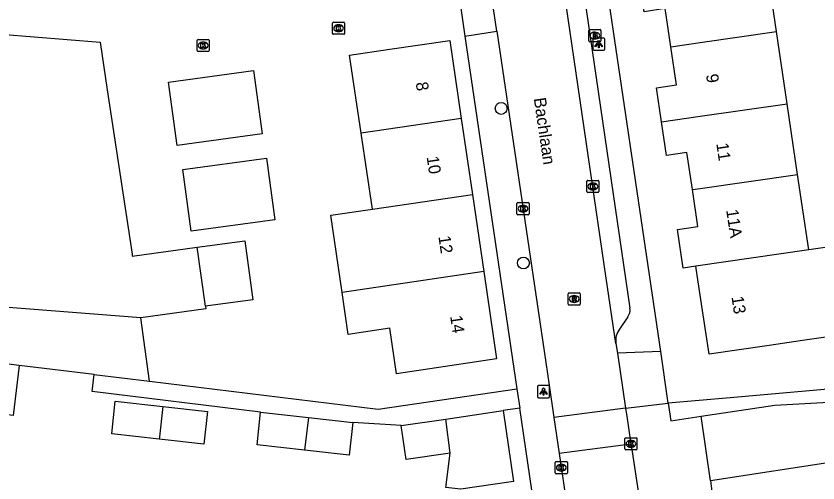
# Model space of a CAD drawing. Extents: x 159053 to 160041, y 380450 to 381422.
# Drawn here: x 159443.6 to 159509.7, y 381207.2 to 381245.7 of the extents above; entities that cross this region are included whole.
import ezdxf

# ---------------------------------------------------------------- set-up
doc = ezdxf.new("R2010")
doc.units = 0
for name, color, linetype in [('IMGEO_Boom', 7, 'Continuous'), ('IMGEO_Brandkraan', 7, 'Continuous'), ('IMGEO_Kolk', 7, 'Continuous'), ('IMGEO_Lichtpunt', 7, 'Continuous'), ('IMGEO_Openbare_ruimte_label', 7, 'Continuous'), ('IMGEO_Pand', 7, 'Continuous'), ('IMGEO_Pand_nummerreeks', 7, 'Continuous'), ('IMGEO_Rijbaan_lokaal_open', 7, 'Continuous'), ('IMGEO_Rioolput', 7, 'Continuous'), ('IMGEO_Voetpad_open', 7, 'Continuous')]:
    doc.layers.add(name, color=color, linetype=linetype)

msp = doc.modelspace()

# ---------------------------------------------------------------- linework, layer by layer
at = {"layer": 'IMGEO_Boom'}
for centre in [(159483.6, 381238.048), (159485.436, 381225.309)]:
    msp.add_circle(centre, 0.489, dxfattribs=at)
at = {"layer": 'IMGEO_Brandkraan'}
for p, q in [((159490.822, 381243.628), (159490.822, 381244.48)), ((159490.897, 381244.554), (159491.749, 381244.554)), ((159491.823, 381244.48), (159491.823, 381243.628)), ((159491.31, 381244.334), (159491.335, 381244.334)), ((159491.749, 381243.554), (159490.897, 381243.554)), ((159491.333, 381243.774), (159491.308, 381243.774))]:
    msp.add_line(p, q, dxfattribs=at)
for points in [[(159490.822, 381243.628), (159490.822, 381244.48)], [(159490.897, 381244.554), (159491.749, 381244.554)], [(159491.823, 381244.48), (159491.823, 381243.628)], [(159491.17, 381244.254), (159491.17, 381243.854), (159491.383, 381243.854)], [(159491.401, 381244.254), (159491.17, 381244.254)], [(159491.349, 381244.173), (159491.295, 381244.173), (159491.295, 381244.097)], [(159491.295, 381244.097), (159491.348, 381244.097)], [(159491.357, 381244.021), (159491.295, 381244.021), (159491.295, 381243.94)], [(159491.295, 381243.94), (159491.357, 381243.94)], [(159491.749, 381243.554), (159490.897, 381243.554)]]:
    msp.add_lwpolyline(points, dxfattribs=at)
for centre, radius, start, end in [((159490.899, 381244.478), 0.0765, 91.55205, 178.44795), ((159490.899, 381244.478), 0.0765, 91.55205, 178.44795), ((159491.747, 381244.478), 0.0765, 1.55205, 88.44795), ((159491.747, 381244.478), 0.0765, 1.55205, 88.44795), ((159491.35, 381244.135), 0.0379, 267.82845, 90.93552), ((159491.358, 381243.98), 0.0404, 269.87594, 90.50774), ((159491.389, 381244.105), 0.251, 268.66757, 293.53466), ((159491.405, 381244.109), 0.145, 59.4692, 91.53667), ((159491.43, 381244.156), 0.0922, 285.51372, 58.15012), ((159491.435, 381243.964), 0.105, 301.31148, 78.98903), ((159490.899, 381243.63), 0.0765, 181.55205, 268.44795), ((159490.899, 381243.63), 0.0765, 181.55205, 268.44795), ((159491.747, 381243.63), 0.0765, 271.55205, 358.44795), ((159491.747, 381243.63), 0.0765, 271.55205, 358.44795)]:
    msp.add_arc(centre, radius, start, end, dxfattribs=at)
for centre, major_axis, ratio, start_param, end_param in [((159491.309, 381244.054), (-0.387, 0.002), 0.722429, 4.712389, 7.853982), ((159491.334, 381244.054), (-0.39, 0.002), 0.717154, 1.570796, 4.712389)]:
    msp.add_ellipse(centre, major_axis=major_axis, ratio=ratio, start_param=start_param, end_param=end_param, dxfattribs=at)
at = {"layer": 'IMGEO_Kolk'}
for p, q in [((159469.776, 381245.161), (159470.628, 381245.161)), ((159469.701, 381244.235), (159469.701, 381245.087)), ((159470.189, 381244.941), (159470.214, 381244.941)), ((159470.702, 381245.087), (159470.702, 381244.235)), ((159470.628, 381244.161), (159469.776, 381244.161)), ((159470.212, 381244.381), (159470.187, 381244.381)), ((159458.545, 381242.813), (159458.545, 381243.665)), ((159458.62, 381243.739), (159459.472, 381243.739)), ((159459.033, 381243.519), (159459.058, 381243.519)), ((159459.546, 381243.665), (159459.546, 381242.813)), ((159459.472, 381242.739), (159458.62, 381242.739)), ((159459.056, 381242.959), (159459.031, 381242.959)), ((159490.655, 381231.192), (159490.655, 381232.044)), ((159490.73, 381232.118), (159491.582, 381232.118)), ((159491.656, 381232.044), (159491.656, 381231.192)), ((159491.166, 381231.338), (159491.141, 381231.338)), ((159491.143, 381231.898), (159491.168, 381231.898)), ((159491.582, 381231.118), (159490.73, 381231.118)), ((159484.903, 381229.361), (159484.903, 381230.213)), ((159484.978, 381230.287), (159485.83, 381230.287)), ((159485.391, 381230.067), (159485.416, 381230.067)), ((159485.904, 381230.213), (159485.904, 381229.361)), ((159485.83, 381229.287), (159484.978, 381229.287)), ((159485.414, 381229.507), (159485.389, 381229.507)), ((159493.793, 381209.974), (159493.793, 381210.826)), ((159493.868, 381210.9), (159494.72, 381210.9)), ((159494.794, 381210.826), (159494.794, 381209.974)), ((159494.304, 381210.12), (159494.279, 381210.12)), ((159494.281, 381210.68), (159494.306, 381210.68)), ((159494.72, 381209.9), (159493.868, 381209.9)), ((159488.059, 381208.008), (159488.059, 381208.86)), ((159488.134, 381208.934), (159488.986, 381208.934)), ((159489.06, 381208.86), (159489.06, 381208.008)), ((159488.57, 381208.154), (159488.545, 381208.154)), ((159488.547, 381208.714), (159488.572, 381208.714)), ((159488.986, 381207.934), (159488.134, 381207.934))]:
    msp.add_line(p, q, dxfattribs=at)
for points in [[(159469.776, 381245.161), (159470.628, 381245.161)], [(159469.701, 381244.235), (159469.701, 381245.087)], [(159470.022, 381244.861), (159470.145, 381244.861), (159470.145, 381244.71), (159470.275, 381244.861), (159470.439, 381244.861), (159470.293, 381244.71), (159470.446, 381244.461), (159470.294, 381244.461), (159470.209, 381244.625), (159470.145, 381244.558), (159470.145, 381244.461), (159470.022, 381244.461), (159470.022, 381244.861)], [(159470.702, 381245.087), (159470.702, 381244.235)], [(159470.628, 381244.161), (159469.776, 381244.161)], [(159458.545, 381242.813), (159458.545, 381243.665)], [(159458.62, 381243.739), (159459.472, 381243.739)], [(159458.866, 381243.439), (159458.989, 381243.439), (159458.989, 381243.288), (159459.119, 381243.439), (159459.283, 381243.439), (159459.137, 381243.288), (159459.29, 381243.039), (159459.138, 381243.039), (159459.053, 381243.203), (159458.989, 381243.136), (159458.989, 381243.039), (159458.866, 381243.039), (159458.866, 381243.439)], [(159459.546, 381243.665), (159459.546, 381242.813)], [(159459.472, 381242.739), (159458.62, 381242.739)], [(159490.655, 381231.192), (159490.655, 381232.044)], [(159490.73, 381232.118), (159491.582, 381232.118)], [(159491.656, 381232.044), (159491.656, 381231.192)], [(159490.976, 381231.818), (159491.099, 381231.818), (159491.099, 381231.667), (159491.229, 381231.818), (159491.393, 381231.818), (159491.247, 381231.667), (159491.4, 381231.418), (159491.248, 381231.418), (159491.163, 381231.582), (159491.099, 381231.515), (159491.099, 381231.418), (159490.976, 381231.418), (159490.976, 381231.818)], [(159491.582, 381231.118), (159490.73, 381231.118)], [(159484.903, 381229.361), (159484.903, 381230.213)], [(159484.978, 381230.287), (159485.83, 381230.287)], [(159485.224, 381229.987), (159485.347, 381229.987), (159485.347, 381229.836), (159485.477, 381229.987), (159485.641, 381229.987), (159485.495, 381229.836), (159485.648, 381229.587), (159485.496, 381229.587), (159485.411, 381229.751), (159485.347, 381229.684), (159485.347, 381229.587), (159485.224, 381229.587), (159485.224, 381229.987)], [(159485.904, 381230.213), (159485.904, 381229.361)], [(159485.83, 381229.287), (159484.978, 381229.287)], [(159493.793, 381209.974), (159493.793, 381210.826)], [(159493.868, 381210.9), (159494.72, 381210.9)], [(159494.794, 381210.826), (159494.794, 381209.974)], [(159494.114, 381210.6), (159494.237, 381210.6), (159494.237, 381210.449), (159494.367, 381210.6), (159494.531, 381210.6), (159494.385, 381210.449), (159494.538, 381210.2), (159494.386, 381210.2), (159494.301, 381210.364), (159494.237, 381210.297), (159494.237, 381210.2), (159494.114, 381210.2), (159494.114, 381210.6)], [(159494.72, 381209.9), (159493.868, 381209.9)], [(159488.059, 381208.008), (159488.059, 381208.86)], [(159488.134, 381208.934), (159488.986, 381208.934)], [(159489.06, 381208.86), (159489.06, 381208.008)], [(159488.38, 381208.634), (159488.503, 381208.634), (159488.503, 381208.483), (159488.633, 381208.634), (159488.797, 381208.634), (159488.651, 381208.483), (159488.804, 381208.234), (159488.652, 381208.234), (159488.567, 381208.398), (159488.503, 381208.331), (159488.503, 381208.234), (159488.38, 381208.234), (159488.38, 381208.634)], [(159488.986, 381207.934), (159488.134, 381207.934)]]:
    msp.add_lwpolyline(points, dxfattribs=at)
for centre, start, end in [((159469.778, 381245.085), 91.55205, 178.44795), ((159469.778, 381245.085), 91.55205, 178.44795), ((159470.626, 381245.085), 1.55205, 88.44795), ((159470.626, 381245.085), 1.55205, 88.44795), ((159469.778, 381244.237), 181.55205, 268.44795), ((159469.778, 381244.237), 181.55205, 268.44795), ((159470.626, 381244.237), 271.55205, 358.44795), ((159470.626, 381244.237), 271.55205, 358.44795), ((159458.622, 381243.663), 91.55205, 178.44795), ((159458.622, 381243.663), 91.55205, 178.44795), ((159459.47, 381243.663), 1.55205, 88.44795), ((159459.47, 381243.663), 1.55205, 88.44795), ((159458.622, 381242.815), 181.55205, 268.44795), ((159458.622, 381242.815), 181.55205, 268.44795), ((159459.47, 381242.815), 271.55205, 358.44795), ((159459.47, 381242.815), 271.55205, 358.44795), ((159490.732, 381232.042), 91.55205, 178.44795), ((159490.732, 381232.042), 91.55205, 178.44795), ((159491.58, 381232.042), 1.55205, 88.44795), ((159491.58, 381232.042), 1.55205, 88.44795), ((159490.732, 381231.194), 181.55205, 268.44795), ((159490.732, 381231.194), 181.55205, 268.44795), ((159491.58, 381231.194), 271.55205, 358.44795), ((159491.58, 381231.194), 271.55205, 358.44795), ((159484.98, 381230.211), 91.55205, 178.44795), ((159484.98, 381230.211), 91.55205, 178.44795), ((159485.828, 381230.211), 1.55205, 88.44795), ((159485.828, 381230.211), 1.55205, 88.44795), ((159484.98, 381229.363), 181.55205, 268.44795), ((159484.98, 381229.363), 181.55205, 268.44795), ((159485.828, 381229.363), 271.55205, 358.44795), ((159485.828, 381229.363), 271.55205, 358.44795), ((159493.87, 381210.824), 91.55205, 178.44795), ((159493.87, 381210.824), 91.55205, 178.44795), ((159494.718, 381210.824), 1.55205, 88.44795), ((159494.718, 381210.824), 1.55205, 88.44795), ((159493.87, 381209.976), 181.55205, 268.44795), ((159493.87, 381209.976), 181.55205, 268.44795), ((159494.718, 381209.976), 271.55205, 358.44795), ((159494.718, 381209.976), 271.55205, 358.44795), ((159488.136, 381208.858), 91.55205, 178.44795), ((159488.136, 381208.858), 91.55205, 178.44795), ((159488.984, 381208.858), 1.55205, 88.44795), ((159488.984, 381208.858), 1.55205, 88.44795), ((159488.136, 381208.01), 181.55205, 268.44795), ((159488.136, 381208.01), 181.55205, 268.44795), ((159488.984, 381208.01), 271.55205, 358.44795), ((159488.984, 381208.01), 271.55205, 358.44795)]:
    msp.add_arc(centre, 0.0765, start, end, dxfattribs=at)
for centre, major_axis, ratio, start_param, end_param in [((159470.188, 381244.661), (-0.387, 0.002), 0.722429, 4.712389, 7.853982), ((159470.213, 381244.661), (-0.39, 0.002), 0.717154, 1.570796, 4.712389), ((159459.032, 381243.239), (-0.387, 0.002), 0.722429, 4.712389, 7.853982), ((159459.057, 381243.239), (-0.39, 0.002), 0.717154, 1.570796, 4.712389), ((159491.142, 381231.618), (-0.387, 0.002), 0.722429, 4.712389, 7.853982), ((159491.167, 381231.618), (-0.39, 0.002), 0.717154, 1.570796, 4.712389), ((159485.39, 381229.787), (-0.387, 0.002), 0.722429, 4.712389, 7.853982), ((159485.415, 381229.787), (-0.39, 0.002), 0.717154, 1.570796, 4.712389), ((159494.28, 381210.4), (-0.387, 0.002), 0.722429, 4.712389, 7.853982), ((159494.305, 381210.4), (-0.39, 0.002), 0.717154, 1.570796, 4.712389), ((159488.546, 381208.434), (-0.387, 0.002), 0.722429, 4.712389, 7.853982), ((159488.571, 381208.434), (-0.39, 0.002), 0.717154, 1.570796, 4.712389)]:
    msp.add_ellipse(centre, major_axis=major_axis, ratio=ratio, start_param=start_param, end_param=end_param, dxfattribs=at)
at = {"layer": 'IMGEO_Lichtpunt'}
for p, q in [((159492.048, 381243.853), (159491.24, 381243.853)), ((159492.048, 381243.853), (159491.24, 381243.853)), ((159491.146, 381243.758), (159491.146, 381242.951)), ((159491.146, 381243.758), (159491.146, 381242.951)), ((159492.142, 381242.951), (159492.142, 381243.758)), ((159492.142, 381242.951), (159492.142, 381243.758)), ((159491.24, 381242.857), (159492.048, 381242.857)), ((159491.24, 381242.857), (159492.048, 381242.857)), ((159486.593, 381215.106), (159486.593, 381214.299)), ((159486.593, 381215.106), (159486.593, 381214.299)), ((159487.495, 381215.201), (159486.687, 381215.201)), ((159487.495, 381215.201), (159486.687, 381215.201)), ((159487.589, 381214.299), (159487.589, 381215.106)), ((159487.589, 381214.299), (159487.589, 381215.106)), ((159486.687, 381214.205), (159487.495, 381214.205)), ((159486.687, 381214.205), (159487.495, 381214.205))]:
    msp.add_line(p, q, dxfattribs=at)
for points in [[(159491.52, 381243.422), (159491.559, 381243.394), (159491.371, 381243.132), (159491.333, 381243.159), (159491.52, 381243.422)], [(159491.622, 381243.374), (159491.669, 381243.374), (159491.669, 381243.052), (159491.622, 381243.052), (159491.622, 381243.374)], [(159491.732, 381243.394), (159491.77, 381243.421), (159491.957, 381243.159), (159491.918, 381243.131), (159491.732, 381243.394)], [(159486.967, 381214.77), (159487.006, 381214.742), (159486.818, 381214.48), (159486.78, 381214.507), (159486.967, 381214.77)], [(159487.179, 381214.742), (159487.217, 381214.769), (159487.404, 381214.507), (159487.365, 381214.479), (159487.179, 381214.742)], [(159487.069, 381214.722), (159487.116, 381214.722), (159487.116, 381214.4), (159487.069, 381214.4), (159487.069, 381214.722)]]:
    msp.add_lwpolyline(points, dxfattribs=at)
for centre in [(159491.645, 381243.556), (159487.092, 381214.904)]:
    msp.add_circle(centre, 0.0994, dxfattribs=at)
for centre, start, end in [((159491.24, 381243.758), 90, 180), ((159491.24, 381243.758), 90, 180), ((159492.048, 381243.758), 0, 90), ((159492.048, 381243.758), 0, 90), ((159491.24, 381242.951), 180, 270), ((159491.24, 381242.951), 180, 270), ((159492.048, 381242.951), 270, 0), ((159492.048, 381242.951), 270, 360), ((159486.687, 381215.106), 90, 180), ((159486.687, 381215.106), 90, 180), ((159487.495, 381215.106), 0, 90), ((159487.495, 381215.106), 0, 90), ((159486.687, 381214.299), 180, 270), ((159486.687, 381214.299), 180, 270), ((159487.495, 381214.299), 270, 0), ((159487.495, 381214.299), 270, 360)]:
    msp.add_arc(centre, 0.0946, start, end, dxfattribs=at)
at = {"layer": 'IMGEO_Pand'}
for points in [[(159506.294, 381244.383), (159505.466, 381250), (159505.416, 381250.342)], [(159497.584, 381243.132), (159497.121, 381246.276), (159495.392, 381246.022), (159494.986, 381248.845)], [(159442.411, 381244.175), (159450.548, 381243.517), (159451.14, 381239.591), (159453.182, 381226.043), (159453.205, 381225.876), (159458.563, 381226.605)], [(159497.584, 381243.132), (159500, 381243.479), (159506.294, 381244.383)], [(159507.17, 381238.442), (159506.294, 381244.383)], [(159472.063, 381236.011), (159471.115, 381242.447), (159474.414, 381242.933), (159479.36, 381243.661), (159480.307, 381237.228)], [(159496.814, 381236.955), (159496.403, 381239.746), (159498.047, 381239.988), (159497.584, 381243.132)], [(159463.199, 381241.178), (159463.92, 381235.956), (159456.91, 381234.989), (159456.189, 381240.211), (159463.199, 381241.178)], [(159496.814, 381236.955), (159500, 381237.412), (159507.17, 381238.442)], [(159508.031, 381232.603), (159507.17, 381238.442)], [(159480.307, 381237.228), (159472.063, 381236.011)], [(159480.307, 381237.228), (159481.23, 381230.965)], [(159499.361, 381231.358), (159498.911, 381234.412), (159497.225, 381234.163), (159496.814, 381236.955)], [(159472.985, 381229.748), (159472.063, 381236.011)], [(159464.269, 381233.949), (159464.961, 381228.868), (159458.069, 381227.93), (159457.377, 381233.011), (159464.269, 381233.949)], [(159499.361, 381231.358), (159500, 381231.45), (159508.031, 381232.603)], [(159508.949, 381226.38), (159508.031, 381232.603)], [(159499.649, 381225.04), (159498.606, 381224.89), (159498.14, 381228.057), (159499.811, 381228.303), (159499.361, 381231.358)], [(159472.985, 381229.748), (159481.23, 381230.965)], [(159481.23, 381230.965), (159482.166, 381224.604)], [(159470.494, 381222.883), (159469.558, 381229.242), (159472.985, 381229.748)], [(159517.514, 381227.633), (159508.949, 381226.38)], [(159458.563, 381226.605), (159462.483, 381227.139), (159463.144, 381222.283), (159459.224, 381221.75)], [(159459.224, 381221.75), (159458.563, 381226.605)], [(159508.949, 381226.38), (159499.649, 381225.04)], [(159518.269, 381222.285), (159515.681, 381221.905), (159515.219, 381221.543), (159512.65, 381219.528), (159508.441, 381218.912), (159505.687, 381218.509), (159500.739, 381217.784), (159500, 381222.663), (159499.649, 381225.04)], [(159482.166, 381224.604), (159483.228, 381217.393), (159478.282, 381216.665), (159474.983, 381216.179), (159474.432, 381219.923), (159471.004, 381219.421), (159470.494, 381222.883)], [(159482.166, 381224.604), (159470.494, 381222.883)], [(159453.896, 381220.798), (159440.873, 381221.815)], [(159459.224, 381221.75), (159459.254, 381221.532), (159453.896, 381220.798)], [(159454.61, 381215.559), (159453.896, 381220.798)], [(159443.885, 381216.867), (159443.382, 381212.742), (159437.736, 381213.431), (159438.239, 381217.555)], [(159443.885, 381216.867), (159440.57, 381217.271)], [(159450.073, 381216.112), (159443.885, 381216.867)], [(159450.073, 381216.112), (159454.61, 381215.559)], [(159455.415, 381210.79), (159451.506, 381211.228), (159451.806, 381213.909), (159455.734, 381213.469)], [(159455.734, 381213.469), (159459.402, 381213.059), (159459.102, 381210.377), (159455.415, 381210.79)], [(159455.734, 381213.469), (159455.438, 381210.981), (159455.415, 381210.79)], [(159500.075, 381212.689), (159506.152, 381213.58), (159511.097, 381213.852)], [(159511.097, 381213.852), (159511.592, 381208.987), (159500.858, 381207.35)], [(159467.392, 381209.888), (159463.482, 381210.326), (159463.782, 381213.007)], [(159463.782, 381213.007), (159467.711, 381212.567)], [(159483.757, 381213.137), (159484.616, 381207.298), (159480.282, 381206.66), (159479.028, 381206.806), (159479.388, 381209.64)], [(159479.036, 381212.442), (159483.757, 381213.137)], [(159467.711, 381212.567), (159467.392, 381209.888)], [(159471.378, 381212.157), (159471.078, 381209.475), (159467.392, 381209.888)], [(159467.711, 381212.567), (159471.378, 381212.157)], [(159475.358, 381211.9), (159479.036, 381212.442)], [(159479.388, 381209.64), (159479.036, 381212.442)], [(159500.858, 381207.35), (159500.075, 381212.689)], [(159479.388, 381209.64), (159475.769, 381209.107), (159475.358, 381211.9)]]:
    msp.add_lwpolyline(points, dxfattribs=at)
at = {"layer": 'IMGEO_Rijbaan_lokaal_open'}
for points in [[(159493.062, 381218.662), (159492.258, 381224.048), (159488.473, 381250), (159486.847, 381261.146), (159486.669, 381262.342)], [(159483.241, 381244.433), (159482.532, 381249.232)], [(159483.241, 381244.433), (159487.143, 381218.031), (159487.557, 381215.23), (159487.948, 381212.582)], [(159493.062, 381218.662), (159493.18, 381217.872)], [(159493.18, 381217.872), (159493.859, 381213.326)], [(159463.782, 381213.007), (159449.9, 381214.7), (159450.073, 381216.112)], [(159454.61, 381215.559), (159473.478, 381213.258), (159484.891, 381214.936)], [(159484.891, 381214.936), (159485.126, 381213.338)], [(159485.126, 381213.338), (159483.757, 381213.137)], [(159493.859, 381213.326), (159487.948, 381212.582)], [(159493.859, 381213.326), (159493.983, 381212.494), (159494.299, 381210.378)], [(159475.358, 381211.9), (159471.378, 381212.157)], [(159487.948, 381212.582), (159488.389, 381209.601)], [(159494.299, 381210.378), (159488.389, 381209.601)], [(159494.299, 381210.378), (159494.366, 381209.923), (159494.908, 381206.294)], [(159488.389, 381209.601), (159489.023, 381205.31), (159489.612, 381201.327), (159489.808, 381199.999), (159491.467, 381188.558)]]:
    msp.add_lwpolyline(points, dxfattribs=at)
at = {"layer": 'IMGEO_Rioolput'}
for p, q in [((159489.114, 381221.917), (159489.114, 381222.769)), ((159489.189, 381222.843), (159490.041, 381222.843)), ((159490.115, 381222.769), (159490.115, 381221.917)), ((159489.625, 381222.063), (159489.6, 381222.063)), ((159489.602, 381222.623), (159489.627, 381222.623)), ((159490.041, 381221.843), (159489.189, 381221.843))]:
    msp.add_line(p, q, dxfattribs=at)
for points in [[(159489.114, 381221.917), (159489.114, 381222.769)], [(159489.189, 381222.843), (159490.041, 381222.843)], [(159490.115, 381222.769), (159490.115, 381221.917)], [(159489.703, 381222.541), (159489.451, 381222.543), (159489.451, 381222.143)], [(159489.451, 381222.143), (159489.575, 381222.143), (159489.575, 381222.305), (159489.586, 381222.305)], [(159489.629, 381222.462), (159489.575, 381222.462), (159489.575, 381222.381)], [(159489.575, 381222.381), (159489.627, 381222.381)], [(159489.633, 381222.276), (159489.704, 381222.143), (159489.844, 381222.143), (159489.779, 381222.269)], [(159490.041, 381221.843), (159489.189, 381221.843)]]:
    msp.add_lwpolyline(points, dxfattribs=at)
for centre, radius, start, end in [((159489.191, 381222.767), 0.0765, 91.55205, 178.44795), ((159489.191, 381222.767), 0.0765, 91.55205, 178.44795), ((159490.039, 381222.767), 0.0765, 1.55205, 88.44795), ((159490.039, 381222.767), 0.0765, 1.55205, 88.44795), ((159489.585, 381222.252), 0.0533, 26.02933, 88.69889), ((159489.611, 381222.57), 0.19, 274.7715, 282.96867), ((159489.635, 381222.366), 0.0964, 77.00612, 93.18647), ((159489.649, 381222.423), 0.0378, 276.66336, 79.67722), ((159489.702, 381222.431), 0.109, 350.36119, 89.41601), ((159489.7, 381222.431), 0.112, 277.58423, 350.98172), ((159489.684, 381222.216), 0.108, 29.51342, 73.79051), ((159489.191, 381221.919), 0.0765, 181.55205, 268.44795), ((159489.191, 381221.919), 0.0765, 181.55205, 268.44795), ((159490.039, 381221.919), 0.0765, 271.55205, 358.44795), ((159490.039, 381221.919), 0.0765, 271.55205, 358.44795)]:
    msp.add_arc(centre, radius, start, end, dxfattribs=at)
for centre, major_axis, ratio, start_param, end_param in [((159489.601, 381222.343), (-0.387, 0.002), 0.722429, 4.712389, 7.853982), ((159489.626, 381222.343), (-0.39, 0.002), 0.717154, 1.570796, 4.712389)]:
    msp.add_ellipse(centre, major_axis=major_axis, ratio=ratio, start_param=start_param, end_param=end_param, dxfattribs=at)
at = {"layer": 'IMGEO_Voetpad_open'}
for points in [[(159496.747, 381218.013), (159492.045, 381250), (159489.62, 381266.493)], [(159488.271, 381262.261), (159490.06, 381250), (159494.208, 381221.574)], [(159479.909, 381248.818), (159480.617, 381244.005)], [(159480.617, 381244.005), (159483.241, 381244.433)], [(159480.617, 381244.005), (159484.891, 381214.936)], [(159494.041, 381220.86), (159493.349, 381219.861)], [(159496.747, 381218.013), (159493.18, 381217.872)], [(159497.37, 381213.76), (159496.747, 381218.013)], [(159519.236, 381215.683), (159502.476, 381214.202), (159497.37, 381213.76)], [(159493.859, 381213.326), (159497.37, 381213.76)], [(159497.37, 381213.76), (159497.586, 381212.288), (159500.075, 381212.689)], [(159489.16, 381185.654), (159488.937, 381187.416), (159485.126, 381213.338)], [(159500.858, 381207.35), (159501.731, 381200.343), (159501.781, 381199.94), (159502.275, 381199.186), (159503.375, 381189.182), (159503.677, 381187.045)]]:
    msp.add_lwpolyline(points, dxfattribs=at)
for centre, radius, start, end in [((159493.215, 381221.43), 1.004, 325.40727, 8.26381), ((159494.717, 381218.9), 1.672, 144.90906, 188.16816)]:
    msp.add_arc(centre, radius, start, end, dxfattribs=at)

# ---------------------------------------------------------------- texts
at = {"layer": 'IMGEO_Openbare_ruimte_label'}
msp.add_text('Bachlaan', height=1, rotation=278.39757, dxfattribs=at).set_placement((159486.284, 381238.877))
at = {"layer": 'IMGEO_Pand_nummerreeks'}
for s, rotation, p in [('9', 278.47744, (159500.476, 381240.823)), ('8', 278.37669, (159476.558, 381240.168)), ('11', 278.47744, (159501.322, 381235.145)), ('10', 278.37669, (159477.458, 381234.057)), ('11A', 278.47744, (159502.138, 381229.67)), ('12', 278.37669, (159478.424, 381227.496)), ('13', 278.5408, (159502.577, 381222.515)), ('14', 278.37669, (159479.392, 381220.926))]:
    msp.add_text(s, height=1, rotation=rotation, dxfattribs=at).set_placement(p)

doc.saveas('drawing.dxf')
